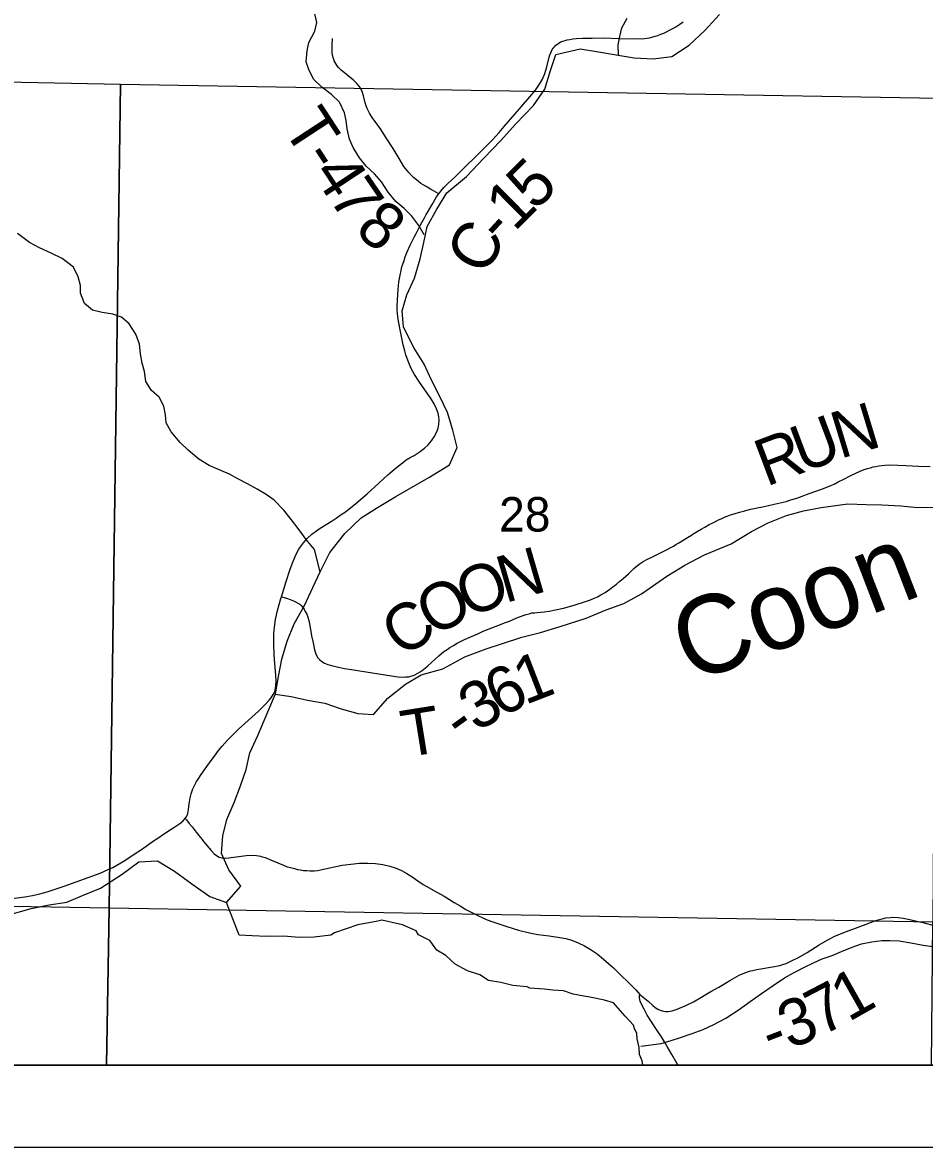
# Model space of a CAD drawing. Extents: x 0 to 34, y -8.9 to 22.
# Drawn here: x 28.944 to 30.038, y 14.5 to 15.866 of the extents above; entities that cross this region are included whole.
import ezdxf

# ---------------------------------------------------------------- set-up
doc = ezdxf.new("R2010")
doc.units = 0
for name, color, linetype in [('GM_X_Corporation', 7, 'Continuous'), ('GM_X_County_Road', 7, 'Continuous'), ('GM_X_County_Road_Text', 7, 'Continuous'), ('GM_X_Minor_River', 7, 'Continuous'), ('GM_X_Minor_River_Text', 7, 'Continuous'), ('GM_X_Section_Text', 7, 'Continuous'), ('GM_X_Township_Road', 7, 'Continuous'), ('GM_X_Township_Road_Text', 7, 'Continuous'), ('SH_Data', 7, 'Continuous')]:
    doc.layers.add(name, color=color, linetype=linetype)

msp = doc.modelspace()

# ---------------------------------------------------------------- linework, layer by layer
at = {"layer": 'GM_X_Corporation'}
msp.add_lwpolyline([(23.7167, 14.6), (30.5167, 14.6), (30.5167, 16.7663), (30.4571, 16.7673), (29.5528, 16.7835), (28.3182, 16.8002)], dxfattribs=at)
for points in [[(28.1739, 14.6), (30.5167, 14.6), (30.5167, 16.7663), (30.4571, 16.7673), (29.5528, 16.7835), (28.3182, 16.8002), (28.1928, 16.8054), (28.1817, 16.6637), (28.1846, 16.3341), (28.1918, 16.1509), (28.1809, 15.2987)], [(29.0629, 15.7906), (29.0488, 14.7907), (28.1732, 14.8057), (28.1747, 14.9791), (28.1775, 15.2925), (28.1801, 15.6079), (28.182, 15.8086)], [(30.056, 15.7737), (30.0487, 14.7736), (29.0488, 14.7907), (29.0629, 15.7906)], [(28.1707, 14.6), (29.0457, 14.6), (29.0488, 14.7907), (28.1732, 14.8057), (28.1713, 14.6617)], [(29.0457, 14.6), (30.0469, 14.6), (30.0487, 14.7736), (29.0488, 14.7907)]]:
    msp.add_lwpolyline(points, close=True, dxfattribs=at)
at = {"layer": 'GM_X_County_Road'}
for points in [[(29.4491, 15.6577), (29.4514, 15.6609), (29.453, 15.6629), (29.4554, 15.6656), (29.4607, 15.6709), (29.4676, 15.6772), (29.4751, 15.6845), (29.5, 15.7089), (29.5109, 15.7198), (29.5145, 15.7236), (29.5181, 15.7277), (29.5222, 15.7322), (29.5282, 15.7393), (29.5415, 15.7549), (29.5492, 15.7638), (29.5596, 15.7754), (29.5663, 15.7835), (29.5712, 15.7906), (29.5748, 15.797), (29.5776, 15.8038), (29.5801, 15.812), (29.5835, 15.8253), (29.5844, 15.828), (29.5856, 15.8307), (29.5868, 15.8327), (29.5879, 15.8345), (29.5894, 15.8363), (29.5912, 15.838), (29.593, 15.8395), (29.5952, 15.8409), (29.5973, 15.842), (29.5996, 15.843), (29.6025, 15.8439), (29.6049, 15.8446), (29.6082, 15.8452), (29.6118, 15.8458), (29.6159, 15.8461), (29.6234, 15.8466), (29.6352, 15.8468), (29.6489, 15.847), (29.6681, 15.8464), (29.6849, 15.846), (29.6913, 15.8461), (29.6948, 15.846), (29.6988, 15.8463), (29.7015, 15.8466), (29.7046, 15.8472), (29.7075, 15.8478), (29.7115, 15.8489), (29.7147, 15.8498), (29.7186, 15.8513), (29.722, 15.8528), (29.7252, 15.8542), (29.7292, 15.8562), (29.7329, 15.8582), (29.7367, 15.8605), (29.7414, 15.8637), (29.7454, 15.8664)], [(29.258, 15.1686), (29.2636, 15.1872), (29.2681, 15.2007), (29.2709, 15.2084), (29.2747, 15.2176), (29.2774, 15.2233), (29.2792, 15.2264), (29.281, 15.2292), (29.2848, 15.2342), (29.2868, 15.2366), (29.2894, 15.2393), (29.295, 15.2444), (29.2995, 15.2479), (29.3052, 15.2517), (29.3194, 15.2606), (29.3246, 15.264), (29.3307, 15.2682), (29.3357, 15.2718), (29.3483, 15.2818), (29.3621, 15.2933), (29.3762, 15.3064), (29.3871, 15.3164), (29.3975, 15.3253), (29.4048, 15.3312), (29.4094, 15.3346), (29.4144, 15.3376), (29.419, 15.3402), (29.4263, 15.3448), (29.4317, 15.3489), (29.4362, 15.353), (29.4401, 15.3577), (29.4435, 15.3627), (29.4462, 15.3681), (29.4481, 15.3733), (29.4491, 15.378), (29.4495, 15.3828), (29.4492, 15.3869), (29.4482, 15.3916), (29.4463, 15.3968), (29.4434, 15.4028), (29.4389, 15.4102), (29.4322, 15.4198), (29.4246, 15.4304), (29.4195, 15.4383), (29.4156, 15.4455), (29.4126, 15.4524), (29.4106, 15.4578), (29.4091, 15.4622), (29.4076, 15.4672), (29.4058, 15.4744), (29.4016, 15.4946), (29.3997, 15.5056), (29.3989, 15.5125), (29.3986, 15.5173), (29.3984, 15.5212), (29.3987, 15.5287), (29.3991, 15.5355), (29.3997, 15.5416), (29.4002, 15.5464), (29.4007, 15.5505), (29.4015, 15.5549), (29.402, 15.559), (29.4034, 15.5646), (29.4043, 15.5691), (29.4053, 15.5723), (29.4068, 15.5769), (29.4083, 15.5812), (29.4106, 15.5872), (29.4141, 15.5953), (29.4174, 15.602), (29.4194, 15.6059), (29.4214, 15.6097), (29.4234, 15.6135), (29.4251, 15.6167), (29.4269, 15.6202), (29.4283, 15.6228), (29.4301, 15.6255), (29.4315, 15.6284), (29.4338, 15.6325), (29.4352, 15.6352), (29.4408, 15.6448), (29.4463, 15.6539), (29.4491, 15.6577)], [(29.1412, 14.8994), (29.1431, 14.9024), (29.1444, 14.9056), (29.1453, 14.9103), (29.1457, 14.914), (29.1464, 14.9195), (29.1472, 14.9245), (29.1485, 14.9294), (29.1506, 14.9353), (29.1521, 14.9388), (29.1551, 14.9443), (29.1578, 14.9485), (29.1605, 14.9527), (29.1655, 14.9598), (29.1727, 14.9698), (29.1768, 14.9751), (29.1817, 14.9818), (29.1861, 14.9871), (29.1927, 14.9945), (29.197, 14.9991), (29.202, 15.0037), (29.2061, 15.0079), (29.21, 15.0114), (29.2138, 15.0148), (29.2303, 15.0298), (29.2392, 15.0385), (29.2433, 15.0431), (29.2455, 15.046), (29.248, 15.0501), (29.2495, 15.0528), (29.2503, 15.0551), (29.2508, 15.0576), (29.2512, 15.0604), (29.2516, 15.0665), (29.2514, 15.0732), (29.25, 15.0874), (29.2491, 15.098), (29.2487, 15.1111), (29.2489, 15.1236), (29.2495, 15.1317), (29.2509, 15.1409), (29.2533, 15.1519), (29.2573, 15.1663), (29.258, 15.1686)], [(28.9246, 14.8014), (28.9467, 14.8042), (28.9558, 14.8058), (28.9649, 14.8079), (28.9738, 14.8104), (28.9943, 14.8174), (29.0236, 14.8277), (29.0381, 14.8332), (29.0478, 14.8374), (29.0533, 14.8399), (29.0582, 14.8427), (29.0678, 14.8484), (29.0818, 14.8575), (29.0869, 14.8611), (29.091, 14.8639), (29.0967, 14.8679), (29.1027, 14.8721), (29.1079, 14.8755), (29.115, 14.8804), (29.1228, 14.8855), (29.1275, 14.8885), (29.1347, 14.8933), (29.1384, 14.8963), (29.1412, 14.8994)], [(29.1412, 14.8994), (29.1428, 14.8977), (29.1462, 14.8934), (29.1495, 14.8892), (29.1547, 14.8828), (29.1577, 14.8789), (29.1617, 14.8739), (29.1634, 14.8714), (29.1641, 14.8707)], [(29.1641, 14.8707), (29.1679, 14.8661), (29.1726, 14.8605), (29.1765, 14.8566), (29.1793, 14.8544), (29.1823, 14.8526), (29.184, 14.852), (29.1857, 14.8517), (29.1875, 14.8515), (29.1898, 14.8514), (29.1941, 14.8517), (29.2151, 14.8545), (29.222, 14.8548), (29.2277, 14.8545), (29.2326, 14.8536), (29.2335, 14.8533)], [(29.2335, 14.8533), (29.2381, 14.852), (29.2468, 14.8485), (29.2605, 14.8427), (29.2648, 14.8408), (29.2692, 14.8397), (29.2737, 14.8385), (29.2776, 14.8375), (29.2809, 14.8369), (29.2848, 14.8363), (29.2888, 14.8361), (29.2931, 14.8357), (29.2977, 14.8357), (29.3018, 14.8362), (29.3056, 14.8371), (29.3317, 14.8426), (29.3422, 14.8441), (29.3528, 14.845), (29.3628, 14.8452), (29.3722, 14.8447), (29.3809, 14.8435), (29.3895, 14.8415), (29.3972, 14.8391), (29.4036, 14.8364), (29.4102, 14.8328), (29.418, 14.8276), (29.4235, 14.8239), (29.4302, 14.8194), (29.4338, 14.8171), (29.4428, 14.812), (29.4554, 14.8049), (29.4618, 14.8011), (29.4677, 14.7976), (29.4749, 14.7933), (29.482, 14.7889), (29.493, 14.7831), (29.5065, 14.7769), (29.5145, 14.7738), (29.5315, 14.7681), (29.5458, 14.7638), (29.559, 14.7606), (29.5693, 14.7586), (29.5828, 14.7568), (29.5958, 14.7551), (29.6032, 14.7536), (29.6092, 14.7519), (29.618, 14.7485), (29.6259, 14.7448), (29.634, 14.7401), (29.6412, 14.7351), (29.649, 14.7288), (29.661, 14.7179), (29.688, 14.6914), (29.6931, 14.6857)], [(29.6931, 14.6857), (29.703, 14.6775), (29.7088, 14.6722), (29.7118, 14.6698), (29.7148, 14.668), (29.7177, 14.6666), (29.7216, 14.6654), (29.7243, 14.6649), (29.7274, 14.6651), (29.7322, 14.6659), (29.7385, 14.668), (29.7488, 14.6724), (29.7581, 14.677), (29.7692, 14.6835), (29.7793, 14.6894), (29.7889, 14.6947), (29.7969, 14.6995), (29.8024, 14.7028), (29.8079, 14.7061), (29.8134, 14.709), (29.8203, 14.7121), (29.8262, 14.7141), (29.8348, 14.7162), (29.8563, 14.7196), (29.8629, 14.7211), (29.8665, 14.7221), (29.8705, 14.7235), (29.8772, 14.7264), (29.8855, 14.7306), (29.8961, 14.7369), (29.9108, 14.7462), (29.9211, 14.7521), (29.9306, 14.7568), (29.9439, 14.7623), (29.9613, 14.7688), (29.9794, 14.7754), (29.9824, 14.7763), (29.9871, 14.7777), (29.9914, 14.7787), (29.9971, 14.7792), (30.0013, 14.7795), (30.0066, 14.7792), (30.0128, 14.7784), (30.0208, 14.7769), (30.0292, 14.7749), (30.0365, 14.7731), (30.0514, 14.769)]]:
    msp.add_lwpolyline(points, dxfattribs=at)
at = {"layer": 'GM_X_Minor_River'}
for points in [[(29.4314, 15.608), (29.4247, 15.6194), (29.4164, 15.6304), (29.4069, 15.6399), (29.397, 15.6483), (29.3876, 15.6598), (29.3793, 15.6723), (29.371, 15.6818), (29.3607, 15.6914), (29.3528, 15.7012), (29.3449, 15.7138), (29.3408, 15.7242), (29.3379, 15.7365), (29.3364, 15.7465), (29.3346, 15.7561), (29.3283, 15.7689), (29.3188, 15.7784), (29.307, 15.7873), (29.2975, 15.7965), (29.2915, 15.8074), (29.2881, 15.8178), (29.2894, 15.8311), (29.2914, 15.8413), (29.2984, 15.855), (29.3008, 15.8656), (29.2986, 15.8763)], [(29.4191, 15.4704), (29.4063, 15.4958), (29.4044, 15.5155), (29.4104, 15.5349), (29.4195, 15.5554), (29.4263, 15.5786), (29.4309, 15.5987), (29.435, 15.618), (29.4468, 15.6389), (29.4589, 15.6587), (29.4827, 15.6788), (29.5035, 15.7008), (29.5243, 15.7224), (29.5421, 15.7422), (29.564, 15.765), (29.5776, 15.7847), (29.5844, 15.8075), (29.5912, 15.8268), (29.6204, 15.8337), (29.6404, 15.8306), (29.662, 15.8268), (29.6862, 15.8226), (29.7093, 15.8215), (29.732, 15.8245), (29.7528, 15.8382), (29.772, 15.856), (29.7898, 15.8754)], [(29.6672, 15.8261), (29.6668, 15.8384), (29.6688, 15.8486), (29.6711, 15.8591), (29.6777, 15.871)], [(29.3049, 15.1989), (29.298, 15.226), (29.2882, 15.2379), (29.2796, 15.2497), (29.2702, 15.2619), (29.2608, 15.2737), (29.2491, 15.2856), (29.2395, 15.2925), (29.2284, 15.2991), (29.2169, 15.3057), (29.2053, 15.3119), (29.1949, 15.3173), (29.1845, 15.3219), (29.1703, 15.3278), (29.1576, 15.3356), (29.1448, 15.3464), (29.1353, 15.356), (29.124, 15.3686), (29.118, 15.3796), (29.1173, 15.3895), (29.1155, 15.3998), (29.1098, 15.4107), (29.1003, 15.4188), (29.0935, 15.4297), (29.0918, 15.442), (29.0892, 15.4523), (29.087, 15.4635), (29.0856, 15.4753), (29.0815, 15.4873), (29.0733, 15.4998), (29.0638, 15.5079), (29.0536, 15.5117), (29.0404, 15.5138), (29.0287, 15.5166), (29.0192, 15.5246), (29.014, 15.537), (29.014, 15.5465), (29.0114, 15.5569), (29.0055, 15.5686), (28.9918, 15.5791), (28.9784, 15.5857), (28.9642, 15.5921), (28.9523, 15.5987), (28.9379, 15.6096)], [(28.9327, 14.7839), (28.9542, 14.7903), (28.9762, 14.7945), (28.9974, 14.7979), (29.0166, 14.8059), (29.0386, 14.815), (29.0647, 14.8317), (29.0851, 14.8469), (29.1078, 14.8481), (29.1282, 14.8355), (29.1494, 14.82), (29.1713, 14.8048), (29.1914, 14.7975), (29.2088, 14.8173), (29.194, 14.837), (29.1853, 14.8568), (29.1869, 14.8784), (29.1918, 14.8982), (29.2005, 14.9187), (29.2084, 14.9392), (29.2152, 14.9589), (29.2198, 14.9791), (29.2292, 15.0003), (29.2417, 15.0288), (29.2508, 15.0508), (29.255, 15.0736), (29.2584, 15.0926), (29.2648, 15.1146), (29.2735, 15.1355), (29.286, 15.1579), (29.2962, 15.1799), (29.3049, 15.1989), (29.3166, 15.2221), (29.3348, 15.2452), (29.3548, 15.2642), (29.3745, 15.2767), (29.3968, 15.2904), (29.4369, 15.3132), (29.4619, 15.3287), (29.4713, 15.3496), (29.466, 15.3709), (29.4596, 15.3921), (29.4498, 15.4126), (29.4403, 15.4316), (29.4312, 15.451), (29.4191, 15.4704)], [(29.2506, 15.0504), (29.2697, 15.0474), (29.2898, 15.0432), (29.3106, 15.0394), (29.3306, 15.0326), (29.3506, 15.0269), (29.3699, 15.0257), (29.387, 15.0455), (29.4085, 15.0626), (29.4278, 15.0736), (29.4539, 15.0812), (29.4808, 15.0956), (29.5065, 15.1055), (29.5262, 15.1119), (29.5496, 15.1195), (29.5723, 15.1252), (29.5965, 15.1324), (29.6279, 15.1427), (29.6521, 15.1526), (29.6737, 15.1605), (29.6952, 15.1723), (29.7259, 15.1936), (29.7478, 15.2068), (29.7716, 15.2194), (29.8038, 15.2327), (29.8287, 15.2478), (29.8488, 15.2581), (29.8711, 15.2672), (29.8915, 15.2729), (29.9131, 15.2767), (29.9456, 15.2812), (29.9676, 15.2805), (29.9869, 15.2801), (30.0099, 15.279), (30.03, 15.2771), (30.0504, 15.2774)], [(29.6967, 14.6), (29.6959, 14.6053), (29.6924, 14.6128), (29.6922, 14.6215), (29.6897, 14.6321), (29.6893, 14.6386), (29.6865, 14.6442), (29.6853, 14.6483), (29.6753, 14.6595), (29.661, 14.6756), (29.6503, 14.6788), (29.6325, 14.6823), (29.6249, 14.6836), (29.6119, 14.6861), (29.6005, 14.69), (29.5876, 14.6909), (29.577, 14.6923), (29.5595, 14.6935), (29.5561, 14.6949), (29.539, 14.6965), (29.5242, 14.7004), (29.5094, 14.7028), (29.4987, 14.7094), (29.4838, 14.7145), (29.4689, 14.7225), (29.4577, 14.733), (29.4466, 14.7396), (29.4381, 14.7512), (29.4244, 14.7581), (29.4216, 14.763), (29.4048, 14.7703), (29.3797, 14.7759), (29.3752, 14.7747), (29.3507, 14.7701), (29.3224, 14.7605), (29.3179, 14.7577), (29.2979, 14.7555), (29.2797, 14.7551), (29.2653, 14.756), (29.2437, 14.7564), (29.2399, 14.7563), (29.2225, 14.7568), (29.2066, 14.7576), (29.1914, 14.7975)], [(29.6941, 14.623), (29.7189, 14.6263), (29.7312, 14.6297), (29.7424, 14.6335), (29.7566, 14.6384), (29.7697, 14.6433), (29.7828, 14.6493), (29.7975, 14.6572), (29.8123, 14.6666), (29.8271, 14.6771), (29.8407, 14.6869), (29.8547, 14.6967), (29.8684, 14.7058), (29.8796, 14.7119), (29.8928, 14.719), (29.9047, 14.7247), (29.9144, 14.729), (29.9263, 14.7331), (29.9379, 14.7381), (29.9506, 14.743), (29.9621, 14.7472), (29.9744, 14.7498), (29.9866, 14.7513), (29.9965, 14.7513), (30.0079, 14.7509), (30.0219, 14.7486), (30.037, 14.7458), (30.0513, 14.7434)]]:
    msp.add_lwpolyline(points, dxfattribs=at)
at = {"layer": 'GM_X_Township_Road'}
for points in [[(29.4491, 15.6577), (29.4483, 15.6581), (29.4425, 15.6612), (29.4388, 15.6632), (29.4336, 15.6664), (29.4302, 15.6685), (29.4273, 15.6704), (29.4245, 15.6725), (29.4219, 15.6746), (29.4189, 15.6772), (29.416, 15.6801), (29.4126, 15.6835), (29.4105, 15.686), (29.4085, 15.6883), (29.4067, 15.6909), (29.4036, 15.6957), (29.4009, 15.7004), (29.3972, 15.7067), (29.3936, 15.7127), (29.3845, 15.7269), (29.3791, 15.7352), (29.377, 15.7383), (29.3727, 15.7443), (29.3681, 15.7502), (29.366, 15.7534), (29.3649, 15.7555), (29.3631, 15.7589), (29.3621, 15.7611), (29.3608, 15.7645), (29.3597, 15.7681), (29.3578, 15.7765), (29.3565, 15.7807), (29.3548, 15.7846), (29.3525, 15.7883), (29.3497, 15.7917), (29.3456, 15.7955), (29.3389, 15.801), (29.3307, 15.8077), (29.3273, 15.8112), (29.3258, 15.8131), (29.3243, 15.8152), (29.3222, 15.819), (29.3212, 15.8219), (29.32, 15.826), (29.3196, 15.8289), (29.3194, 15.8314), (29.3194, 15.8335), (29.3196, 15.837), (29.3198, 15.8407), (29.3199, 15.8438), (29.3199, 15.8462)], [(29.258, 15.1686), (29.2598, 15.1682), (29.2643, 15.167), (29.2688, 15.1652), (29.2725, 15.1637), (29.2752, 15.1624), (29.2781, 15.1609), (29.2803, 15.1594), (29.2821, 15.1579), (29.2845, 15.1551), (29.2856, 15.1534), (29.2868, 15.1508), (29.2887, 15.1473), (29.29, 15.1436), (29.2911, 15.1398), (29.2924, 15.1338), (29.2947, 15.1211), (29.2964, 15.1127), (29.2982, 15.1041), (29.3001, 15.0982), (29.3022, 15.0945), (29.3043, 15.0922), (29.3072, 15.0899), (29.3104, 15.088), (29.3144, 15.0863), (29.3204, 15.0845), (29.3274, 15.083), (29.3344, 15.0815), (29.346, 15.0798), (29.3533, 15.0786), (29.3764, 15.0751), (29.3918, 15.0726), (29.3998, 15.0714), (29.4058, 15.071), (29.4092, 15.0712), (29.4129, 15.0715), (29.4152, 15.0721), (29.4193, 15.0735), (29.4237, 15.0758), (29.4264, 15.0774), (29.4289, 15.0792), (29.4329, 15.0823), (29.4357, 15.0846), (29.449, 15.0968), (29.4552, 15.1019), (29.459, 15.1046), (29.4624, 15.1068), (29.4667, 15.1095), (29.4714, 15.1122), (29.4802, 15.1168), (29.4888, 15.1205), (29.4973, 15.1241), (29.5019, 15.1262), (29.5047, 15.1274), (29.5185, 15.1329), (29.5237, 15.1349), (29.5289, 15.1369), (29.5347, 15.1391), (29.5439, 15.1428), (29.5514, 15.1457), (29.5551, 15.147), (29.5585, 15.148), (29.562, 15.1489), (29.5652, 15.1492), (29.5684, 15.1494), (29.5727, 15.1498), (29.5767, 15.1502), (29.5828, 15.1511), (29.5908, 15.1525), (29.6004, 15.1548), (29.6135, 15.1585), (29.6282, 15.1632), (29.6333, 15.1649), (29.6377, 15.1667), (29.6416, 15.1685), (29.6458, 15.1707), (29.6511, 15.1738), (29.6567, 15.1777), (29.6603, 15.1806), (29.6645, 15.1839), (29.6688, 15.1873), (29.6726, 15.1906), (29.6792, 15.1965), (29.6858, 15.2028), (29.692, 15.208), (29.6971, 15.2115), (29.7014, 15.2139), (29.7093, 15.2176), (29.7165, 15.221), (29.7215, 15.2235), (29.726, 15.2258), (29.7298, 15.2278), (29.7337, 15.2298), (29.7368, 15.2318), (29.7405, 15.2339), (29.7445, 15.2363), (29.7476, 15.2384), (29.751, 15.2406), (29.7557, 15.2435), (29.7577, 15.2449), (29.7624, 15.2478), (29.7676, 15.2508), (29.7719, 15.2532), (29.7772, 15.2561), (29.7809, 15.258), (29.7849, 15.26), (29.7885, 15.2618), (29.7918, 15.2633), (29.7957, 15.2652), (29.7991, 15.2665), (29.8031, 15.268), (29.8073, 15.2693), (29.8138, 15.2711), (29.8204, 15.273), (29.8275, 15.2749), (29.8299, 15.2754), (29.8353, 15.2764), (29.842, 15.2778), (29.8491, 15.2792), (29.856, 15.2808), (29.8632, 15.2826), (29.8704, 15.2843), (29.8764, 15.2862), (29.8835, 15.2884), (29.8899, 15.2906), (29.8987, 15.2937), (29.9145, 15.2994), (29.9199, 15.3014), (29.9249, 15.3035), (29.9288, 15.3054), (29.9338, 15.3079), (29.9407, 15.3114), (29.9481, 15.3153), (29.956, 15.319), (29.9606, 15.3211), (29.9653, 15.3229), (29.9693, 15.3243), (29.9729, 15.3252), (29.976, 15.3262), (29.9795, 15.3268), (29.9832, 15.3274), (29.9869, 15.3279), (29.9904, 15.3283), (29.9956, 15.3285), (30.0061, 15.3284), (30.016, 15.328), (30.0313, 15.3272), (30.0454, 15.3268)], [(29.7396, 14.6), (29.7381, 14.6024), (29.7319, 14.6127), (29.7261, 14.6226), (29.723, 14.6283), (29.7192, 14.6343), (29.7141, 14.6422), (29.7072, 14.6525), (29.7019, 14.6608), (29.6982, 14.6679), (29.6948, 14.6747), (29.6935, 14.6778), (29.6929, 14.6798), (29.6926, 14.6817), (29.6926, 14.6838), (29.6931, 14.6857)]]:
    msp.add_lwpolyline(points, dxfattribs=at)
at = {"layer": 'SH_Data'}
for points in [[(23.6167, 21.5), (30.6167, 21.5), (30.6167, 14.5), (23.6167, 14.5)], [(23.7167, 21.4), (30.5167, 21.4), (30.5167, 14.6), (23.7167, 14.6)]]:
    msp.add_lwpolyline(points, close=True, dxfattribs=at)

# ---------------------------------------------------------------- texts
at = {"layer": 'GM_X_County_Road_Text'}
for s, rotation, p in [('5', 45.0474, (29.566, 15.6359)), ('1', 44.6909, (29.5408, 15.611)), ('C', 61.326, (29.5052, 15.5564)), ('-', 47.4018, (29.5255, 15.5944)), ('1', 29.5196, (29.9461, 14.6518)), ('7', 27.4691, (29.9131, 14.6346)), ('3', 21.4703, (29.8746, 14.6191)), ('-', 21.0715, (29.8524, 14.6106))]:
    msp.add_text(s, height=0.0568, rotation=rotation, dxfattribs=at).set_placement(p)
at = {"layer": 'GM_X_Minor_River_Text'}
msp.add_text('Coon', height=0.0947, rotation=21.0379, dxfattribs=at).set_placement((29.7552, 15.0626))
at = {"layer": 'GM_X_Section_Text'}
msp.add_text('28', height=0.04186, rotation=0, dxfattribs=at).set_placement((29.5222, 15.2477))
at = {"layer": 'GM_X_Township_Road_Text'}
for s, rotation, p in [('T', 303.2016, (29.2583, 15.7379)), ('-', 303.2468, (29.2816, 15.7023)), ('4', 303.4284, (29.2945, 15.6826)), ('7', 304.3622, (29.3144, 15.6526)), ('8', 320.0345, (29.3455, 15.6112)), ('N', 16.8761, (29.9359, 15.3357)), ('U', 20.623, (29.89, 15.3184)), ('R', 20.646, (29.8464, 15.3019)), ('N', 16.1996, (29.5294, 15.1606)), ('O', 21.8501, (29.4844, 15.1424)), ('O', 28.711, (29.4421, 15.1192)), ('C', 34.9946, (29.4053, 15.0933)), ('1', 21.1694, (29.5536, 15.0369)), ('6', 28.4319, (29.5245, 15.021)), ('3', 29.5499, (29.4943, 15.0039)), ('T', 9.0762, (29.4083, 14.9734)), ('-', 35.9258, (29.4768, 14.9911))]:
    msp.add_text(s, height=0.0568, rotation=rotation, dxfattribs=at).set_placement(p)

doc.saveas('drawing.dxf')
